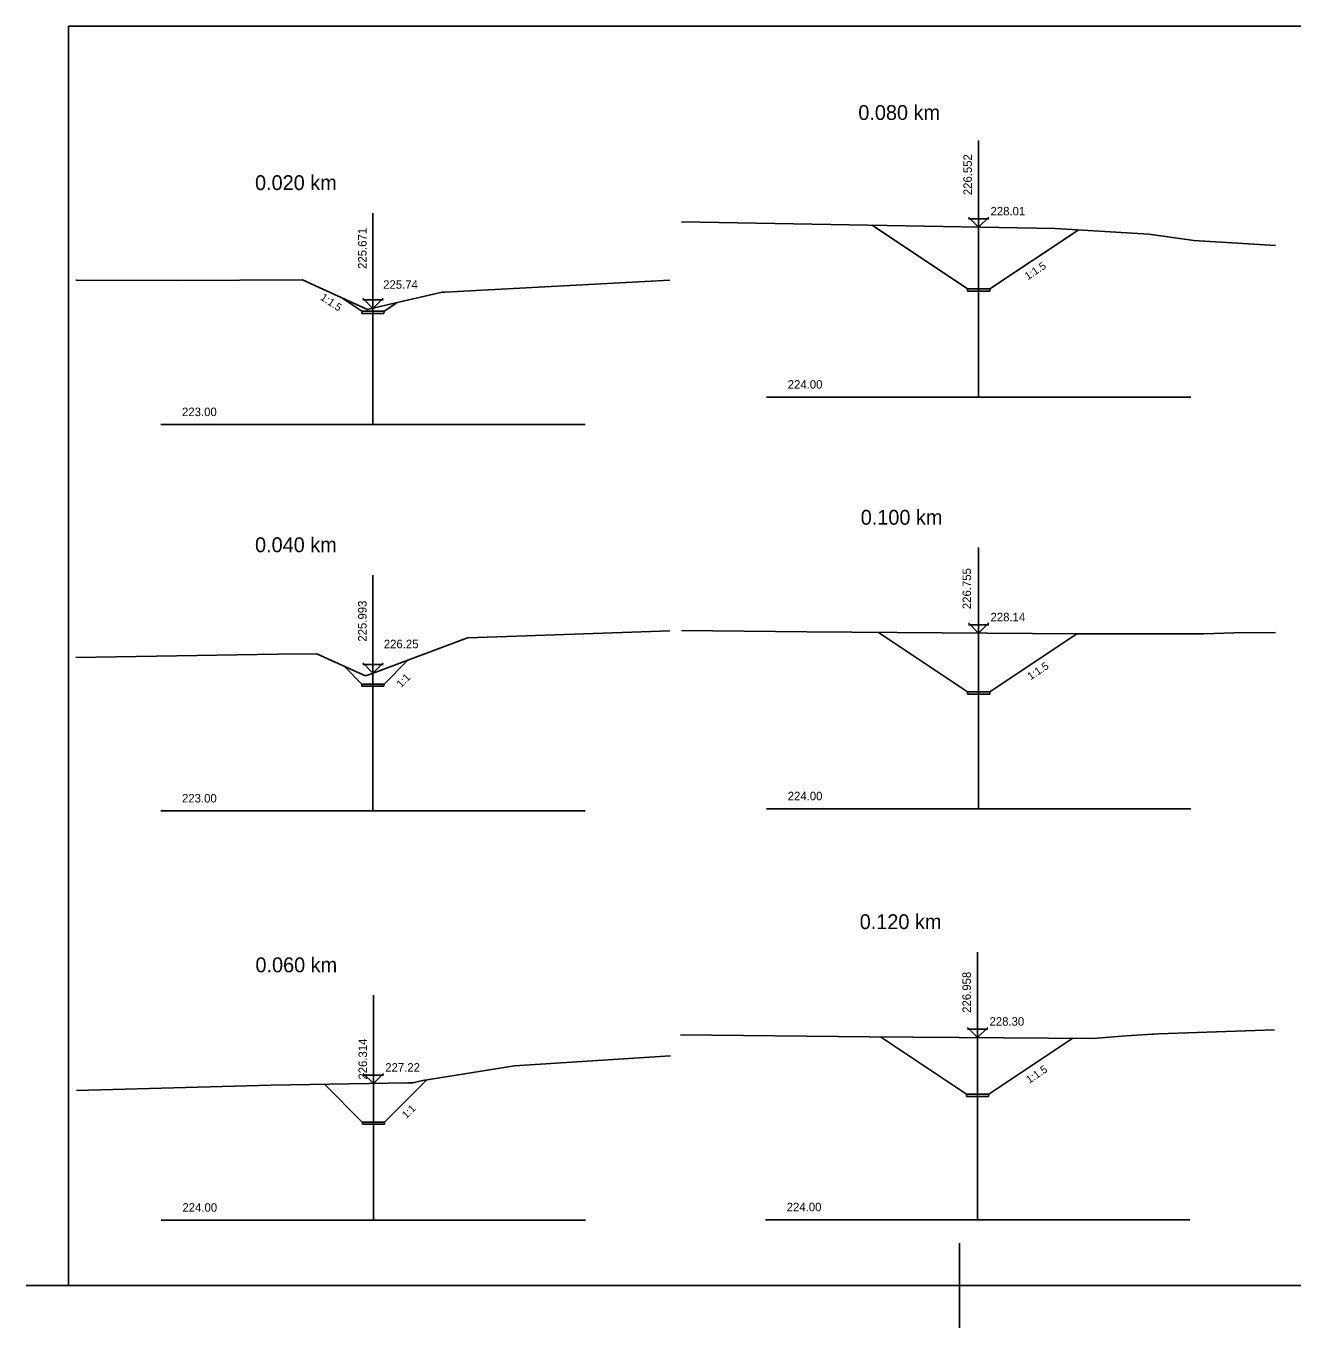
# Model space of a CAD drawing. Extents: x -495905 to -478420, y -1113297 to -1107716.
# Drawn here: x -489388.5 to -489089.9, y -1109801.2 to -1109494.2 of the extents above; entities that cross this region are included whole.
import ezdxf

# ---------------------------------------------------------------- set-up
doc = ezdxf.new("R2010")
doc.units = 0
for name, color, linetype in [('FORMATY', 7, 'Continuous'), ('legenda', 7, 'Continuous'), ('WORKING_LAYER', 7, 'Continuous')]:
    doc.layers.add(name, color=color, linetype=linetype)

msp = doc.modelspace()

# ---------------------------------------------------------------- linework, layer by layer
at = {"layer": 'FORMATY'}
for p, q in [((-489378.45, -1109494.17), (-489378.45, -1109791.17)), ((-489378.45, -1109494.17), (-488748.45, -1109494.17)), ((-489178.45, -1109494.17), (-489158.45, -1109494.17)), ((-489168.45, -1109781.17), (-489168.45, -1109801.17)), ((-489388.45, -1109791.17), (-489368.45, -1109791.17)), ((-489178.45, -1109791.17), (-489158.45, -1109791.17))]:
    msp.add_line(p, q, dxfattribs=at)
at = {"layer": 'legenda'}
msp.add_line((-488748.45, -1109791.17), (-489378.45, -1109791.17), dxfattribs=at)
at = {"layer": 'WORKING_LAYER'}
for p, q in [((-489163.93, -1109581.67), (-489163.93, -1109521.15)), ((-489306.69, -1109588.15), (-489306.69, -1109538.26)), ((-489233.93, -1109540.32), (-489145.92, -1109541.95)), ((-489163.93, -1109541.62), (-489166.33, -1109539.22)), ((-489166.33, -1109539.62), (-489161.53, -1109539.62)), ((-489163.93, -1109541.62), (-489161.53, -1109539.22)), ((-489189.02, -1109541.15), (-489166.54, -1109556.15)), ((-489166.54, -1109556.15), (-489189.02, -1109541.15)), ((-489161.32, -1109556.15), (-489140.51, -1109542.27)), ((-489161.32, -1109556.15), (-489140.51, -1109542.27)), ((-489145.92, -1109541.95), (-489123.82, -1109543.24)), ((-489123.82, -1109543.24), (-489113.24, -1109544.77)), ((-489113.24, -1109544.77), (-489093.93, -1109545.93)), ((-489376.69, -1109554.11), (-489376.57, -1109554.13)), ((-489376.57, -1109554.13), (-489352.93, -1109554.17)), ((-489352.93, -1109554.17), (-489323.29, -1109554.05)), ((-489323.29, -1109554.05), (-489319.35, -1109555.85)), ((-489319.35, -1109555.85), (-489307.95, -1109561.04)), ((-489289.73, -1109556.95), (-489236.69, -1109554.07)), ((-489166.54, -1109556.15), (-489166.53, -1109556.65)), ((-489166.43, -1109556.15), (-489166.53, -1109556.15)), ((-489163.93, -1109556.15), (-489166.43, -1109556.15)), ((-489163.93, -1109556.15), (-489161.43, -1109556.15)), ((-489161.43, -1109556.15), (-489161.33, -1109556.15)), ((-489161.33, -1109556.65), (-489161.32, -1109556.15)), ((-489314.06, -1109558.26), (-489309.3, -1109561.44)), ((-489309.3, -1109561.44), (-489314.06, -1109558.26)), ((-489306.69, -1109560.74), (-489309.09, -1109558.34)), ((-489309.09, -1109558.74), (-489304.29, -1109558.74)), ((-489306.69, -1109560.74), (-489304.29, -1109558.34)), ((-489303.33, -1109559.95), (-489290.41, -1109556.9)), ((-489290.41, -1109556.9), (-489289.73, -1109556.95)), ((-489166.53, -1109556.65), (-489166.43, -1109556.65)), ((-489166.43, -1109556.65), (-489163.93, -1109556.65)), ((-489163.93, -1109556.65), (-489161.43, -1109556.65)), ((-489163.93, -1109556.65), (-489163.93, -1109556.65)), ((-489161.43, -1109556.65), (-489161.33, -1109556.65)), ((-489309.3, -1109561.44), (-489309.29, -1109561.94)), ((-489309.19, -1109561.44), (-489309.29, -1109561.44)), ((-489309.29, -1109561.94), (-489309.19, -1109561.94)), ((-489306.69, -1109561.44), (-489309.19, -1109561.44)), ((-489309.19, -1109561.94), (-489306.69, -1109561.94)), ((-489307.95, -1109561.04), (-489303.33, -1109559.95)), ((-489306.69, -1109561.44), (-489304.19, -1109561.44)), ((-489306.69, -1109561.94), (-489304.19, -1109561.94)), ((-489306.69, -1109561.94), (-489306.69, -1109561.94)), ((-489304.19, -1109561.44), (-489304.09, -1109561.44)), ((-489304.19, -1109561.94), (-489304.09, -1109561.94)), ((-489304.09, -1109561.94), (-489304.08, -1109561.44)), ((-489304.08, -1109561.44), (-489301.05, -1109559.41)), ((-489304.08, -1109561.44), (-489301.05, -1109559.41)), ((-489213.93, -1109581.67), (-489113.93, -1109581.67)), ((-489356.69, -1109588.15), (-489256.69, -1109588.15)), ((-489163.93, -1109678.73), (-489163.93, -1109617.17)), ((-489306.69, -1109679.26), (-489306.69, -1109623.65)), ((-489163.93, -1109637.33), (-489166.33, -1109634.93)), ((-489166.33, -1109635.33), (-489161.53, -1109635.33)), ((-489163.93, -1109637.33), (-489161.53, -1109634.93)), ((-489307.25, -1109646.97), (-489284.44, -1109638.41)), ((-489284.44, -1109638.41), (-489277.45, -1109638.17)), ((-489277.45, -1109638.17), (-489238.89, -1109636.86)), ((-489238.89, -1109636.86), (-489236.69, -1109636.75)), ((-489233.93, -1109636.67), (-489204.44, -1109637.05)), ((-489204.44, -1109637.05), (-489151.27, -1109637.42)), ((-489187.54, -1109637.17), (-489166.54, -1109651.18)), ((-489166.54, -1109651.18), (-489187.54, -1109637.17)), ((-489161.32, -1109651.18), (-489140.76, -1109637.46)), ((-489161.32, -1109651.18), (-489140.76, -1109637.46)), ((-489151.27, -1109637.42), (-489141.32, -1109637.49)), ((-489141.32, -1109637.49), (-489140.88, -1109637.46)), ((-489140.88, -1109637.46), (-489110.88, -1109637.48)), ((-489110.88, -1109637.48), (-489103.77, -1109637.27)), ((-489103.77, -1109637.27), (-489093.93, -1109637.14)), ((-489329.2, -1109642.31), (-489319.92, -1109642.23)), ((-489319.92, -1109642.23), (-489311.46, -1109646.04)), ((-489376.69, -1109643.04), (-489329.2, -1109642.31)), ((-489313.5, -1109645.12), (-489309.3, -1109649.33)), ((-489309.3, -1109649.33), (-489313.5, -1109645.12)), ((-489306.69, -1109646.76), (-489309.09, -1109644.36)), ((-489309.09, -1109644.76), (-489304.29, -1109644.76)), ((-489306.69, -1109646.76), (-489304.29, -1109644.36)), ((-489304.08, -1109649.33), (-489298.41, -1109643.65)), ((-489304.08, -1109649.33), (-489298.41, -1109643.65)), ((-489311.46, -1109646.04), (-489308.44, -1109647.4)), ((-489308.44, -1109647.4), (-489307.25, -1109646.97)), ((-489309.3, -1109649.33), (-489309.29, -1109649.83)), ((-489309.19, -1109649.33), (-489309.29, -1109649.33)), ((-489309.29, -1109649.83), (-489309.19, -1109649.83)), ((-489306.69, -1109649.33), (-489309.19, -1109649.33)), ((-489309.19, -1109649.83), (-489306.69, -1109649.83)), ((-489306.69, -1109649.33), (-489304.19, -1109649.33)), ((-489306.69, -1109649.83), (-489304.19, -1109649.83)), ((-489306.69, -1109649.83), (-489306.69, -1109649.83)), ((-489304.19, -1109649.33), (-489304.09, -1109649.33)), ((-489304.19, -1109649.83), (-489304.09, -1109649.83)), ((-489304.09, -1109649.83), (-489304.08, -1109649.33)), ((-489166.54, -1109651.18), (-489166.53, -1109651.68)), ((-489166.43, -1109651.18), (-489166.53, -1109651.18)), ((-489163.93, -1109651.18), (-489166.43, -1109651.18)), ((-489163.93, -1109651.18), (-489161.43, -1109651.18)), ((-489161.43, -1109651.18), (-489161.33, -1109651.18)), ((-489161.33, -1109651.68), (-489161.32, -1109651.18)), ((-489166.53, -1109651.68), (-489166.43, -1109651.68)), ((-489166.43, -1109651.68), (-489163.93, -1109651.68)), ((-489163.93, -1109651.68), (-489161.43, -1109651.68)), ((-489163.93, -1109651.68), (-489163.93, -1109651.68)), ((-489161.43, -1109651.68), (-489161.33, -1109651.68)), ((-489213.93, -1109678.73), (-489113.93, -1109678.73)), ((-489356.69, -1109679.26), (-489256.69, -1109679.26)), ((-489164.17, -1109775.64), (-489164.17, -1109712.53)), ((-489306.59, -1109775.75), (-489306.59, -1109722.71)), ((-489164.17, -1109732.69), (-489166.57, -1109730.29)), ((-489166.57, -1109730.69), (-489161.77, -1109730.69)), ((-489164.17, -1109732.69), (-489161.77, -1109730.29)), ((-489121.51, -1109731.84), (-489094.17, -1109730.88)), ((-489234.17, -1109732.04), (-489189.7, -1109732.51)), ((-489189.7, -1109732.51), (-489136.97, -1109732.88)), ((-489187.07, -1109732.53), (-489166.78, -1109746.06)), ((-489166.78, -1109746.06), (-489187.07, -1109732.53)), ((-489161.56, -1109746.06), (-489141.75, -1109732.84)), ((-489161.56, -1109746.06), (-489141.75, -1109732.84)), ((-489136.97, -1109732.88), (-489129.17, -1109732.32)), ((-489129.17, -1109732.32), (-489122.99, -1109731.88)), ((-489122.99, -1109731.88), (-489122.75, -1109731.88)), ((-489122.75, -1109731.88), (-489121.51, -1109731.84)), ((-489273.3, -1109739.38), (-489237.8, -1109737.07)), ((-489237.8, -1109737.07), (-489236.59, -1109737.04)), ((-489294.97, -1109742.85), (-489273.3, -1109739.38)), ((-489330.77, -1109743.92), (-489298.5, -1109743.4)), ((-489306.59, -1109743.53), (-489308.99, -1109741.13)), ((-489308.99, -1109741.53), (-489304.19, -1109741.53)), ((-489306.59, -1109743.53), (-489304.19, -1109741.13)), ((-489303.98, -1109752.61), (-489294.08, -1109742.71)), ((-489303.98, -1109752.61), (-489294.08, -1109742.71)), ((-489298.5, -1109743.4), (-489297.31, -1109743.35)), ((-489297.31, -1109743.35), (-489294.97, -1109742.85)), ((-489376.59, -1109745.17), (-489330.77, -1109743.92)), ((-489318.08, -1109743.71), (-489309.2, -1109752.61)), ((-489309.2, -1109752.61), (-489318.08, -1109743.71)), ((-489166.78, -1109746.06), (-489166.77, -1109746.56)), ((-489166.67, -1109746.06), (-489166.77, -1109746.06)), ((-489166.77, -1109746.56), (-489166.67, -1109746.56)), ((-489164.17, -1109746.06), (-489166.67, -1109746.06)), ((-489166.67, -1109746.56), (-489164.17, -1109746.56)), ((-489164.17, -1109746.06), (-489161.67, -1109746.06)), ((-489164.17, -1109746.56), (-489161.67, -1109746.56)), ((-489164.17, -1109746.56), (-489164.17, -1109746.56)), ((-489161.67, -1109746.06), (-489161.57, -1109746.06)), ((-489161.67, -1109746.56), (-489161.57, -1109746.56)), ((-489161.57, -1109746.56), (-489161.56, -1109746.06)), ((-489309.2, -1109752.61), (-489309.19, -1109753.11)), ((-489309.09, -1109752.61), (-489309.19, -1109752.61)), ((-489306.59, -1109752.61), (-489309.09, -1109752.61)), ((-489306.59, -1109752.61), (-489304.09, -1109752.61)), ((-489304.09, -1109752.61), (-489303.99, -1109752.61)), ((-489303.99, -1109753.11), (-489303.98, -1109752.61)), ((-489309.19, -1109753.11), (-489309.09, -1109753.11)), ((-489309.09, -1109753.11), (-489306.59, -1109753.11)), ((-489306.59, -1109753.11), (-489304.09, -1109753.11)), ((-489306.59, -1109753.11), (-489306.59, -1109753.11)), ((-489304.09, -1109753.11), (-489303.99, -1109753.11)), ((-489356.59, -1109775.75), (-489256.59, -1109775.75)), ((-489214.17, -1109775.64), (-489114.17, -1109775.64))]:
    msp.add_line(p, q, dxfattribs=at)

# ---------------------------------------------------------------- texts
for s, height, p in [('    0.080 km', 3.5, (-489197.49, -1109516.31)), ('    0.020 km', 3.5, (-489339.68, -1109532.85)), ('228.01', 2, (-489161.13, -1109538.82)), ('225.74', 2, (-489304.28, -1109556.12)), ('224.00', 2, (-489208.93, -1109579.67)), ('223.00', 2, (-489351.69, -1109586.15)), ('    0.100 km', 3.5, (-489196.92, -1109611.76)), ('    0.040 km', 3.5, (-489339.68, -1109618.24)), ('228.14', 2, (-489161.13, -1109634.53)), ('226.25', 2, (-489304.13, -1109640.88)), ('223.00', 2, (-489351.69, -1109677.26)), ('224.00', 2, (-489208.93, -1109676.73)), ('    0.120 km', 3.5, (-489197.16, -1109707.12)), ('    0.060 km', 3.5, (-489339.58, -1109717.3)), ('228.30', 2, (-489161.37, -1109729.89)), ('227.22', 2, (-489303.79, -1109740.73)), ('224.00', 2, (-489351.59, -1109773.75)), ('224.00', 2, (-489209.17, -1109773.64))]:
    msp.add_text(s, height=height, dxfattribs=at).set_placement(p)
for s, height, rotation, p in [('226.552', 2, 90, (-489165.53, -1109534.05)), ('225.671', 2, 90, (-489308.19, -1109551.44)), ('1:1.5', 1.8, 33.7029, (-489152.32, -1109554.13)), ('1:1.5', 1.8, 326.2549, (-489319.23, -1109558.56)), ('226.755', 2, 90, (-489165.72, -1109631.67)), ('225.993', 2, 90, (-489308.19, -1109639.33)), ('1:1.5', 1.8, 33.7028, (-489151.68, -1109648.47)), ('1:1', 1.8, 45.0504, (-489300.06, -1109650.3)), ('226.958', 2, 90, (-489165.76, -1109726.85)), ('226.314', 2, 90, (-489308.09, -1109742.61)), ('1:1.5', 1.8, 33.7035, (-489152, -1109743.59)), ('1:1', 1.8, 45.0289, (-489298.8, -1109751.94))]:
    msp.add_text(s, height=height, rotation=rotation, dxfattribs=at).set_placement(p)

doc.saveas('drawing.dxf')
